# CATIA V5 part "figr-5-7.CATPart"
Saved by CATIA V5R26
Part number: Part1
Bounding box of the stored display mesh (mm): x 0 to 150, y -70 to 70, z -150 to 69.804
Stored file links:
  D:\_Deepak\CATIA\CATIA V5-6R2016_Deepak\Resources\Part files\Partfiles\c05_catia_v5_6r2016_prt\figr-5-7.CATPart
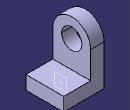
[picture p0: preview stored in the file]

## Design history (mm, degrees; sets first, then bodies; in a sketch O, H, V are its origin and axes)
Set1
  Plane1: type OffsetPt, RefPlane face of Pad2, RefPoint Sketch3
Body1 (main body)
  Sketch1 on yz-plane, origin (0, 0, 0), H (0, 1, 0), V (0, 0, 1)
    arc A1 centre (0, 0) radius 70 from (70, 0) to (-70, 0) ccw
    point P1 (70, 0)
    point P2 (-70, 0)
    line L1 (-70, 0) -> (-70, -150)
    line L2 (-70, -150) -> (70, -150)
    line L3 (70, -150) -> (70, 0)
    circle A2 centre (0, 0) radius 37.5
    radius A1 = 70
    radius A2 = 37.5
    distance O L2 = 150
    coincidence: P1 H, P2 H
    tangency: L1 A1, L3 A1
    horizontal: L2 H
  Pad1: profile Sketch1, direction (1, 0, 0), length 50
  Sketch2 on face of Pad1, origin (50, 0, 0), H (0, 1, 0), V (0, 0, 1)
    line L1 (-70, -150) -> (70, -150)
    line L2 (70, -150) -> (70, -100)
    line L3 (70, -100) -> (-70, -100)
    line L4 (-70, -100) -> (-70, -150)
    reference projected line E1 (-70, -150) -> (70, -150) from edge [face of Pad1 | face of Pad1]
    reference projected line E2 (-70, 0) -> (-70, -150) from edge [face of Pad1 | face of Pad1]
    reference projected line E3 (70, -150) -> (70, 0) from edge [face of Pad1 | face of Pad1]
    length L2 = 50
    horizontal: L1 H, L3 H
    vertical: L2 V, L4 V
    coincidence: L1 E1, E2 L4, L2 E3
  Pad2: profile Sketch2, direction (1, 0, 0), length 100
  Sketch3 on face of Pad2, origin (0, 0, -100), H (1, 0, 0), V (0, 1, 0)
    point P1 (110, 20)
